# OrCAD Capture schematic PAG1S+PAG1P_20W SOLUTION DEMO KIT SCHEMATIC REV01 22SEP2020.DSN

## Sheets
1 PAGE2_REVISION HISTORY: title: CY-SD1125 CYPRESS 20W MOBILE CHARGER DEMO KIT; rev: 01; note: 630-XXXXX-XX
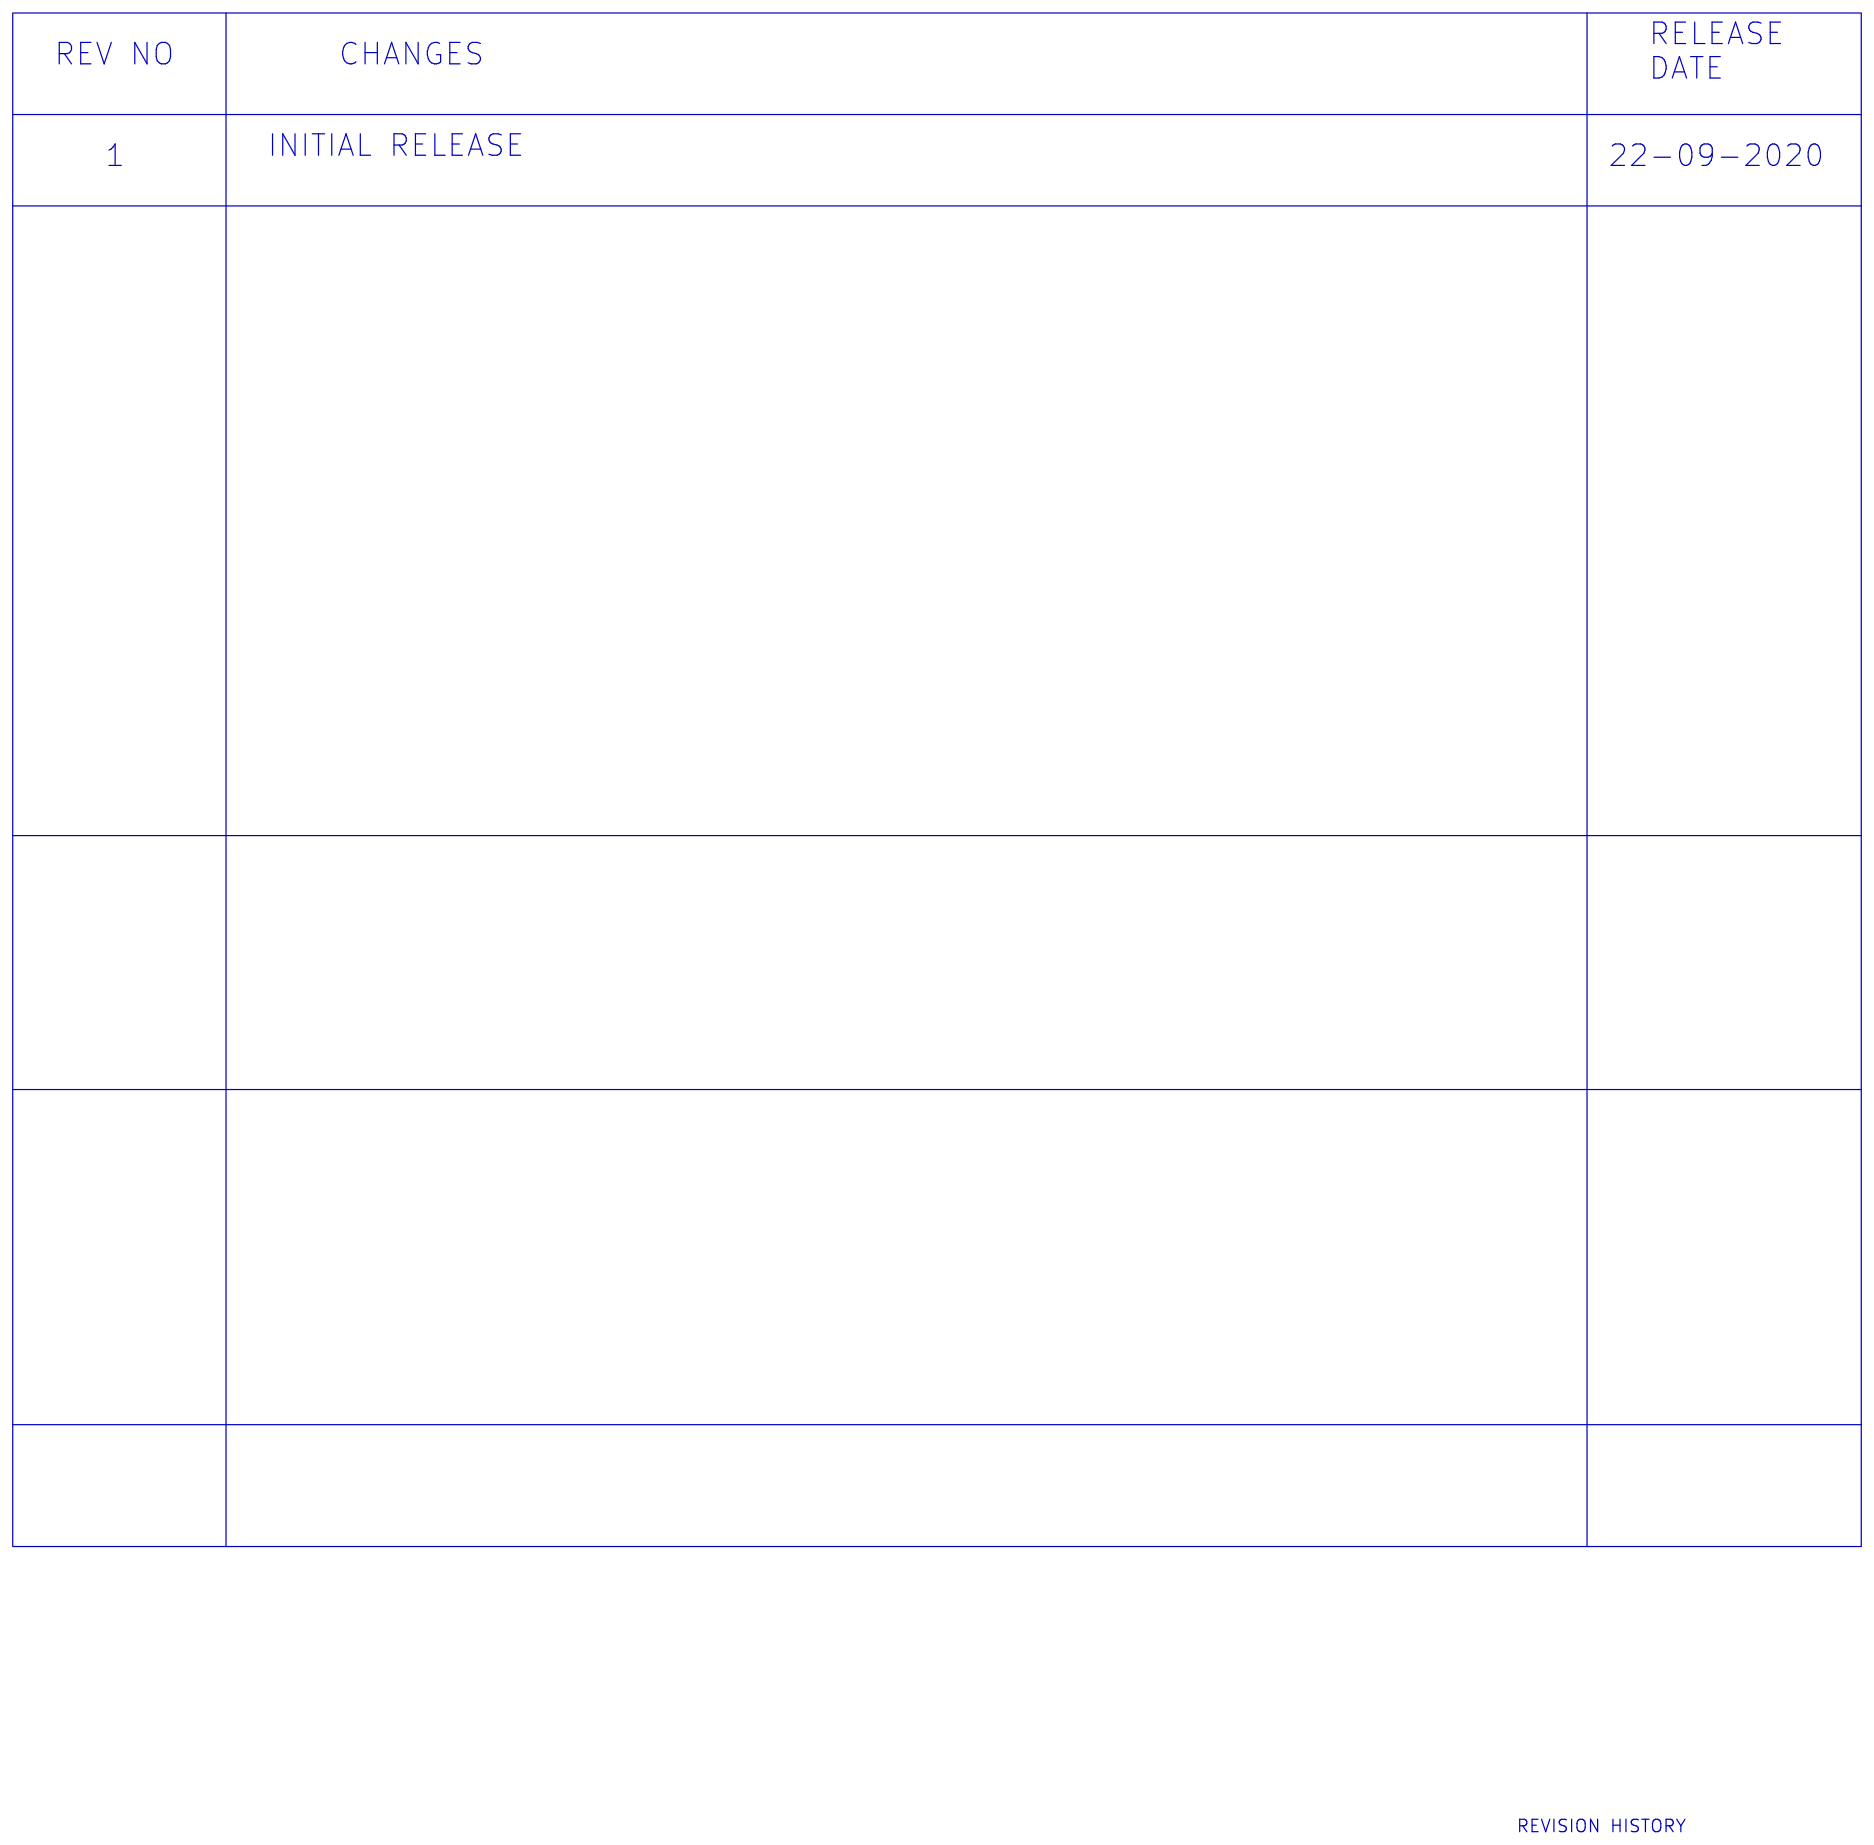
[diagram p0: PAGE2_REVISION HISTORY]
2 PAGE1_PAG1P_PAG1S: size A3
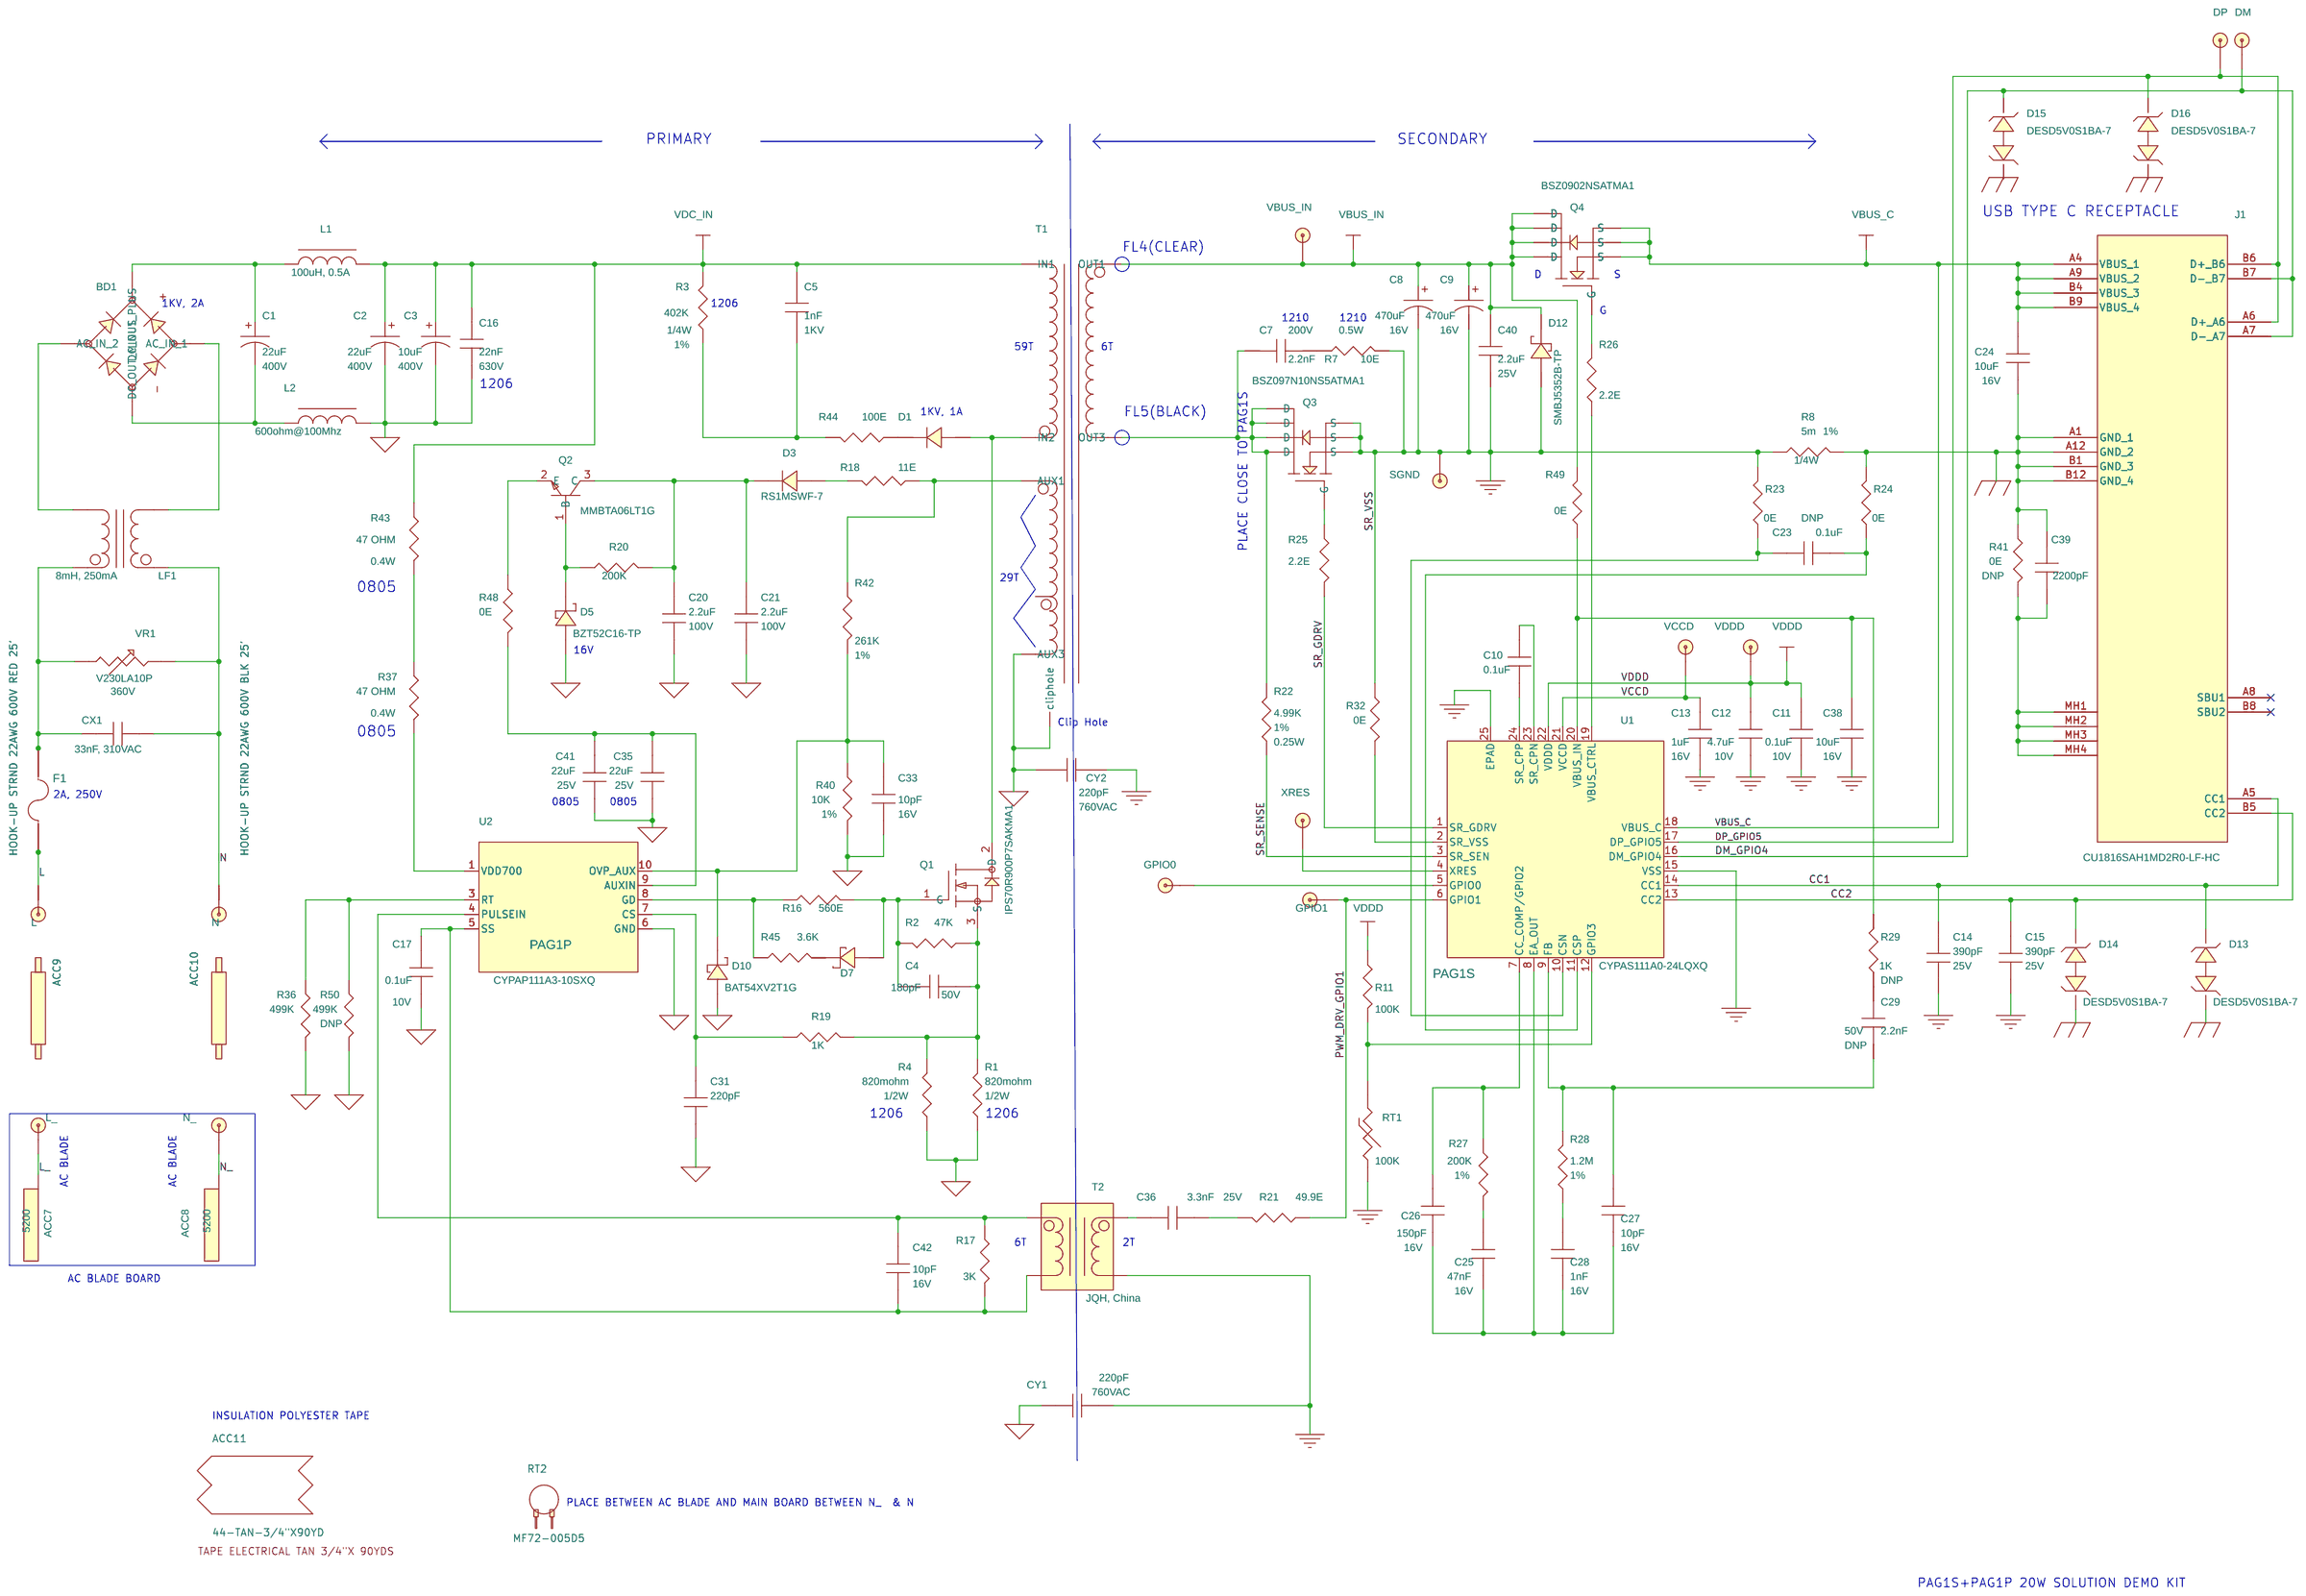
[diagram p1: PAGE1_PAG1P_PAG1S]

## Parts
ACC7  5200  [PCBBLADE]
ACC8  5200  [PCBBLADE]
ACC9  HOOK-UP STRND 22AWG 600V RED 25'
ACC10  HOOK-UP STRND 22AWG 600V BLK 25'
ACC11  44-TAN-3/4"X90YD
BD1  ABS210-13  [SOPA4P400_505X640X170L100X60]
C1  22uF  [CAPPRD600W60D1000H2150]
C2  22uF  [CAPPRD600W60D1000H2150]
C3  10uF  [CAPPRD600W60D1000H2150]
C4  180pF  [capc1608x90n_ty]
C5  1nF  [capc2012x70n_murata]
C7  2.2nF  [1210]
C8  470uF  [CAPPRD250W50D630H1400]
C9  470uF  [CAPPRD250W50D630H1400]
C10  0.1uF  [CAPC1005X56N_CYPS]
C11  0.1uF  [CAPC1005X56N_CYPS]
C12  4.7uF  [CAPC1005X56N_CYPS]
C13  1uF  [CAPC1005X56N_CYPS]
C14  390pF  [CAPC1005X56N_CYPS]
C15  390pF  [CAPC1005X56N_CYPS]
C16  22nF  [SMD_1206]
C17  0.1uF  [capc1608x90n_ty]
C20  2.2uF  [SMD_1206]
C21  2.2uF  [SMD_1206]
C23  0.1uF  [capc1608x90n_ty]
C24  10uF  [capc1608x90n_ty]
C25  47nF  [CAPC1005X56N_CYPS]
C26  150pF  [CAPC1005X56N_CYPS]
C27  10pF  [CAPC1005X56N_CYPS]
C28  1nF  [CAPC1005X56N_CYPS]
C29  2.2nF  [CAPC1005X56N_CYPS]
C31  220pF  [capc1608x90n_ty]
C33  10pF  [capc1608x90n_ty]
C35  22uF  [capc2012x70n_murata]
C36  3.3nF  [CAPC1608X90N_TY]
C38  10uF  [SMD_1206]
C39  2200pF  [capc1608x90n_ty]
C40  2.2uF  [capc2012x70n_murata]
C41  22uF  [capc2012x70n_murata]
C42  10pF  [capc1608x90n_ty]
CX1  33nF, 310VAC  [BFC233820333]
CY1  220pF  [CAPRB750W60L1400T500H1600]
CY2  220pF  [CAPRB750W60L1400T500H1600]
D1  CGRKM4007-HF  [SODFL350X180X115L60X107N]
D3  RS1MSWF-7  [SODFL350X180X115L60X107N]
D5  BZT52C16-TP  [BZT52C12-TP_SOD123]
D7  BAT54J,115  [SODFL250X125X90L60X30N]
D10  BAT54XV2T1G  [BAT54XV2T1G_SOD523]
D12  SMBJ5352B-TP  [DO214AA_MICRO]
D13  DESD5V0S1BA-7  [SOD250X130X110L30X30N]
D14  DESD5V0S1BA-7  [SOD250X130X110L30X30N]
D15  DESD5V0S1BA-7  [SOD250X130X110L30X30N]
D16  DESD5V0S1BA-7  [SOD250X130X110L30X30N]
DM  TEST_POINT  [TP-43R_S]
DP  TEST_POINT  [TP-43R_S]
F1  RSTA 2 AMMO  [FUSRR508W62L885T450H790]
GPIO0  TEST_POINT  [TP-43R_S]
GPIO1  TEST_POINT  [TP-43R_S]
J1  CU1816SAH1MD2R0-LF-HC  [USB-PD_TYPE-C]
L  TEST_POINT  [TP-43R_S]
L1  100uH, 0.5A  [INDRD300W60D800H10001]
L2  600ohm@100Mhz  [resc2012x70n_pec]
L_  TEST_POINT  [TP-43R_S]
LF1  8mH, 250mA  [L3]
N  TEST_POINT  [TP-43R_S]
N_  TEST_POINT  [TP-43R_S]
Q1  IPS70R900P7SAKMA1  [to229p230x654x875-3b]
Q2  MMBTA06LT1G  [SOT23-3P95_240X100L40X44N]
Q3  BSZ097N10NS5ATMA1  [TSDSON65P330X330X110-8N_A]
Q4  BSZ0902NSATMA1  [TSDSON65P330X330X110-8N_A]
R1  820mohm  [resc3216x65n_rohm]
R2  47K  [resc1608x55n_pec]
R3  402K  [RESC3216X65N_ROHM]
R4  820mohm  [resc3216x65n_rohm]
R7  10E  [1210]
R8  5m  [resc3216x65n_rohm]
R11  100K  [resc1608x55n_pec]
R16  560E  [resc1608x55n_pec]
R17  3K  [resc1608x55n_pec]
R18  11E  [RESC1608X55N_PEC]
R19  1K  [resc1608x55n_pec]
R20  200K  [resc1608x55n_pec]
R21  49.9E  [resc1608x55n_pec]
R22  4.99K  [resc1608x55n_pec]
R23  0E  [resc1005x40n_pec]
R24  0E  [resc1005x40n_pec]
R25  2.2E  [resc1608x55n_pec]
R26  2.2E  [resc1608x55n_pec]
R27  200K  [resc1005x40n_pec]
R28  1.2M  [resc1005x40n_pec]
R29  1K  [RESC1005X40N_PEC]
R32  0E  [resc1608x55n_pec]
R36  499K  [resc1608x55n_pec]
R37  47 OHM  [resc2012x70n_pec]
R40  10K  [resc1608x55n_pec]
R41  0E  [RESC1608X55N_PEC]
R42  261K  [RESC1608X55N_PEC]
R43  47 OHM  [resc2012x70n_pec]
R44  100E  [RESC2012X70N_PEC]
R45  3.6K  [resc1608x55n_pec]
R48  0E  [RESC1608X55N_PEC]
R49  0E  [RESC1005X40N_PEC]
R50  499K  [RESC1005X40N_PEC]
RT1  100K  [resc2012x70n_pec]
RT2  MF72-005D5
SGND  TEST_POINT  [TP-43R_S]
T1  RM7  [RM7]
T2  1:3  [RADIAL_R113426000]
U1  PAG1S  [QFN50P400X400X60-25T275X275N]
U2  PAG1P  [SOIC100P600X175-10N_CYPS]
VBUS_IN  TEST_POINT  [TP-43R_S]
VCCD  TEST_POINT  [TP-43R_S]
VDDD  TEST_POINT  [TP-43R_S]
VR1  V230LA10P
XRES  TEST_POINT  [TP-43R_S]

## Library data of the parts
ACC7 ACC8 = HEYCO_PCB_BLADE_5201_0: PCB BLADE SNAP THRU POLARIZED; Manufacturer: Heyco
ACC9 = HOOK-UP_STRND_26AWG_600V_RED: DIGIKEY-PART NUMBER: CN150R-25-ND; MFG Part number: 11047-22-1-0500-004-1-TS; Manufacturer: CNC Tech; Price: 9.15
ACC10 = HOOK-UP_STRND_26AWG_600V_RED: DIGIKEY-PART NUMBER: CN150B-25-ND; MFG Part number: 11047-22-1-0500-001-1-TS; Manufacturer: CNC Tech; Price: 9.15
ACC11 = INSULATION_POLYESTER_TAPE: TAPE ELECTRICAL TAN 3/4"X 90YDS; DIGIKEY-PART NUMBER: 3M157336-ND; Manufacturer: 3M; Price: 19.69
BD1 = BR805D_1: BRIDGE RECT 1PHASE 1KV 2A 4SOPA; DIGIKEY-PART NUMBER: ABS210-13DICT-ND; Manufacturer: Diodes Incorporated; PRICE: 0.5
C1 = CAP_2: CAP ALUM 22uF 400V RADIAL DIA 10X16; MFG Part number: EHS2GM220G16OT; Manufacturer: AISHI; Manufaturer: AISHI; Package: RAD; Voltage: 400V
C2 = CAP_2: CAP ALUM 22uF 400V RADIAL DIA 10X16; MFG Part number: EHS2GM220G16OT; Manufacturer: AISHI; Manufaturer: Rubycon; Package: RAD; Voltage: 400V
C3 = CAP_2: CAP ALUM 10uF 400V RADIAL DIA 10X12.5; Manufaturer: Rubycon; Package: RAD; Voltage: 400V
C4 = 0_0.01uF-50V-10%-X7R-0603: CAP CER 180PF 50V C0G/NPO 0603; DIGIKEY-PART NUMBER: 311-1072-1-ND; MFG Part number: CC0603JRNPO9BN181; Manufacturer: Yageo; Price: 0.1; Voltage: 50V
C5 = 0_0.01uF-50V-10%-X7R-0603: CAP CER 1000PF 1KV X7R 0805; DIGIKEY-PART NUMBER: 399-7137-1-ND; MFG Part number: C0805C102MDRACTU; Manufacturer: KEMET; Price: 0.41; TOLERANCE: <Tolerance>; Voltage: 1KV
C7 = 0_0.01uF-50V-10%-X7R-0603: CAP CER 2200PF 200V NP0 1210; Assy: DNP; DIGIKEY-PART NUMBER: 399-15600-1-ND; MFG Part number: C1210C222J2GAC7800; Manufacturer: KEMET; Price: 0.94; TOLERANCE: <Tolerance>; Voltage: 200V
C8 C9 = CAP_2: CAP POLYMER 470uF 16V 6.3x11; MFG Part number: SPF1CM471E11O00RAXXX; Manufacturer: AISHI; Package: RAD; RATED_VOLTAGE: 16V
C10 C11 = 0_0.01uF-50V-10%-X7R-0603: CAP CER 0.1UF 10V X5R 0402; DIGIKEY-PART NUMBER: 1276-1443-1-ND; MFG Part number: CL05A104MP5NNNC; Manufacturer: Samsung Electro-Mechanics; Price: 0.1; Voltage: 10V
C12 = 0_0.01uF-50V-10%-X7R-0603: CAP CER 4.7UF 10V X5R 0402; DIGIKEY-PART NUMBER: 490-14306-1-ND; MFG Part number: GRM155R61A475MEAAD; Manufacturer: Murata Electronics North America; Price: 0.23; Voltage: 10V
C13 = 0_0.01uF-50V-10%-X7R-0603: CAP CER 1UF 16V X5R 0402; DIGIKEY-PART NUMBER: 1276-1447-1-ND; MFG Part number: CL05A105MO5NNNC; Manufacturer: Samsung Electro-Mechanics; Price: 0.1; Voltage: 16V
C14 C15 = 0_0.01uF-50V-10%-X7R-0603: CAP CER 390PF 25V C0G/NP0 0402; DIGIKEY-PART NUMBER: 490-14801-1-ND; MFG Part number: GRM1555C1E391JA01D; Manufacturer: Murata Electronics North America; Price: 0.13; Voltage: 25V
C16 = 0_0.01uF-50V-10%-X7R-0603: CAP CER 0.022UF 630V X7R 1206; DIGIKEY-PART NUMBER: 1276-3126-1-ND; MFG Part number: CL31B223KHHNNNE; Manufacturer: Samsung Electro-Mechanics; Price: 0.26; TOLERANCE: <Tolerance>; Voltage: 630V
C17 = 0_0.01uF-50V-10%-X7R-0603: CAP CER 0.1UF 10V X7R 0603; DIGIKEY-PART NUMBER: 311-4055-1-ND; MFG Part number: CC0603KRX7R6BB104; Manufacturer: Yageo; Price: 0.12; Voltage: 10V
C20 C21 = 0_0.01uF-50V-10%-X7R-0603: CAP CER 2.2UF 100V X5R 1206; DIGIKEY-PART NUMBER: 1276-2724-1-ND; MFG Part number: CL31A225KC9LNNC; Manufacturer: Samsung Electro-Mechanics; Price: 1.33; Voltage: 100V
C23 = 0_0.01uF-50V-10%-X7R-0603: CAP CER 0.1UF 35V X7R 0603; DIGIKEY-PART NUMBER: 587-3354-1-ND; DNP: DNP; MFG Part number: GMK107B7104KAHT; Manufacturer: Taiyo Yuden; Price: 0.16
C24 = 0_0.01uF-50V-10%-X7R-0603: CAP CER 10UF 16V X5R 0603; DIGIKEY-PART NUMBER: 490-10728-1-ND; MFG Part number: GRM188R61C106KAALD; Manufacturer: Murata Electronics; Price: 0.39; TOLERANCE: <Tolerance>; Voltage: 16V
C25 = 0_0.01uF-50V-10%-X7R-0603: CAP CER 0.047UF 16V X7R 0402; DIGIKEY-PART NUMBER: 1276-1077-1-ND; MFG Part number: CL05B473KO5NNNC; Manufacturer: Samsung Electro-Mechanics; Price: 0.1; Voltage: 16V
C26 = 0_0.01uF-50V-10%-X7R-0603: CAP CER 150PF 16V X7R 0402; DIGIKEY-PART NUMBER: 732-7515-1-ND; MFG Part number: 885012205020; Manufacturer: Wurth Electronics Inc.; PART_NUMBER: 885012205020; Price: 0.1; Voltage: 16V
C27 = 0_0.01uF-50V-10%-X7R-0603: CAP CER 10PF 16V C0G/NP0 0402; DIGIKEY-PART NUMBER: 732-7441-1-ND; MFG Part number: 885012005025; Manufacturer: Wurth Electronics Inc.; Price: 0.1; Voltage: 16V
C28 = 0_0.01uF-50V-10%-X7R-0603: CAP CER 1000PF 16V X7R 0402; DIGIKEY-PART NUMBER: 399-7755-1-ND; MFG Part number: C0402C102K4RACTU; Manufacturer: KEMET; Price: 0.1; Voltage: 16V
C29 = 0_0.01uF-50V-10%-X7R-0603: CAP CER 2200PF 50V X7R 0402; DIGIKEY-PART NUMBER: 490-4914-1-ND; DNP: DNP; MFG Part number: GCM155R71H222KA37D; Manufacturer: Murata Electronics North America; Price: 0.10; TOLERANCE: <Tolerance>; Voltage: 50V
C31 = 0_0.01uF-50V-10%-X7R-0603: CAP CER 220PF 10V C0G/NP0 0603; DIGIKEY-PART NUMBER: 399-14963-1-ND; MFG Part number: C0603C221J8GAC7867; Manufacturer: KEMET; Price: 0.39; Voltage: 10V
C33 C42 = 0_0.01uF-50V-10%-X7R-0603: CAP CER 10PF 16V C0G/NP0 0603; DIGIKEY-PART NUMBER: 732-7760-1-ND; MFG Part number: 885012006017; Manufacturer: Wurth Electronics Inc.; Price: 0.1; Voltage: 16V
C35 C41 = 0_0.01uF-50V-10%-X7R-0603: CAP CER 22UF 25V X5R 0805; DIGIKEY-PART NUMBER: 490-14661-1-ND; MFG Part number: GRM21BR61E226ME44K; Manufacturer: Murata Electronics North America; Price: 0.49; Voltage: 25V
C36 = 0_0.01uF-50V-10%-X7R-0603: CAP CER 3300PF 25V NP0 0603; DIGIKEY-PART NUMBER: 399-15394-1-ND; MFG Part number: C0603C332J3GAC7867; Manufacturer: KEMET; Price: 0.4; TOLERANCE: C0G/NPO; Voltage: 25V
C38 = 0_0.01uF-50V-10%-X7R-0603: CAP CER 10UF 16V X7R 1206; DIGIKEY-PART NUMBER: 1276-6641-1-ND; MFG Part number: CL31B106MOHNNNE; Manufacturer: Samsung Electro-Mechanics; Price: 0.26; TOLERANCE: <Tolerance>; Voltage: 16V
C39 = 0_0.01uF-50V-10%-X7R-0603: CAP CER 2200PF 500V X7R 0603; DIGIKEY-PART NUMBER: 399-14966-1-ND; MFG Part number: C0603C222KCRAC7867; Manufacturer: KEMET; Price: 0.3; TOLERANCE: <Tolerance>; Voltage: 500V
C40 = 0_0.01uF-50V-10%-X7R-0603: CAP CER 2.2UF 25V X5R 0805; DIGIKEY-PART NUMBER: 1276-6458-1-ND; MFG Part number: CL21A225KAFNNNG; Manufacturer: Samsung Electro-Mechanics; Price: 0.17; TOLERANCE: <Tolerance>; Voltage: 25V
CX1 = 0_0.01uF-50V-10%-X7R-0603: CAP FILM 0.033UF 20% 630VDC RAD; DIGIKEY-PART NUMBER: BC1612-ND; Manufacturer: Vishay BC Components; Package: RAD; Price: 1.27; TOLERANCE: <Tolerance>; Voltage: 310VAC
CY1 CY2 = 0_0.01uF-50V-10%-X7R-0603: CAP CER 220PF 760VAC Y5S RADIAL; Assy: DNP; DIGIKEY-PART NUMBER: BC2370-ND; MFG Part number: VY1221K31Y5SQ63V0; Manufacturer: Vishay BC Components; Package: RAD; Price: 0.3; Voltage: 760VAC
D1 = DIODE_13: DIODE GEN PURP 1KV 1A SOD123F; DIGIKEY-PART NUMBER: 641-1514-1-ND; Manufacturer: Comchip Technology; PRICE: 0.36
D3 = DIODE_17: DIODE GEN PURP 1KV 1A SOD123F; DIGIKEY-PART NUMBER: RS1MSWF-7DICT-ND; Manufacturer: Diodes Incorporated; Price: 0.52
D5 = DIODE_SCHOTTKY_19: DIODE ZENER 16V 200MW SOD123; DIGIKEY-PART NUMBER: BZT52C16-TPMSCT-ND; Manufacturer: Micro Commercial Co; Price: 0.21
D7 = DIODE_18: DIODE SCHOTTKY 30V 200MA SOD323F; DIGIKEY-PART NUMBER: 1727-4818-1-ND; Manufacturer: Nexperia USA Inc.; PRICE: 0.33
D10 = DIODE_SCHOTTKY_21: DIODE SCHOTTKY 30V 200MA SOD523; DIGIKEY-PART NUMBER: BAT54XV2T1GOSCT-ND; Manufacturer: ON Semiconductor; Price: 0.23
D12 = DIODE_SCHOTTKY_19: DIODE ZENER 15V 5W DO214AA; DIGIKEY-PART NUMBER: SMBJ5352B-TPMSCT-ND; Manufacturer: Micro Commercial Co; Price: 0.65
D13-D16 = TVS_DIODE_1: TVS DIODE 5V 14V SOD323; DIGIKEY-PART NUMBER: DESD5V0S1BA-7DICT-ND; Manufacturer: Diodes Incorporated; Price: 0.36
DM DP GPIO0 GPIO1 L L_ N N_ SGND VBUS_IN VCCD VDDD XRES = TEST_POINT
F1 = Fuse_2: FUSE BRD MNT 2A 250VAC/63VDC RAD; DIGIKEY-PART NUMBER: 507-1868-1-ND; LatestRevisionDate: 17-Jul-2002; LatestRevisionNote: Re-released for DXP Platform.; Manufacturer: Bel Fuse Inc.; PRICE: 0.32; PackageReference: PIN-W2/E2.8; Published: 8-Jun-2000; Publisher: Altium Limited
J1 = USB-PD_TYPE-C_7: CU18 USB Type-C Receptacle Connector; Manufacturer: CviLux Corporation
L1 = INDUCTOR_PAG1S_1: 100uH D8x10mm 0.5A; Current: 300mA; Manufacturer: Prismatic
L2 = INDUCTOR_PAG1S_1: FERRITE BEAD 600 OHM 0805 1LN; Current: 300mA; DIGIKEY-PART NUMBER: 732-1620-1-ND; MFG Part number: 742792040; Manufacturer: Wurth Electronics Inc.; Manufaturer: Bourns Inc.; PRICE: 0.22
LF1 = INDUCTOR_IRON_8: 8mH / D18.5 * T7.5mm*H18.5 / 250mA; MFG Part number: 9404320301; Manufacturer: Prismatic
Q1 = IPP65R380E6XKSA1_1: MOSFET N-CHANNEL 700V 6A TO251; DIGIKEY-PART NUMBER: IPS70R900P7SAKMA1-ND; Manufacturer: Infineon Technologies
Q2 = 2N1070_1: TRANS NPN 80V 0.5A SOT23; DIGIKEY-PART NUMBER: MMBTA06LT1GOSCT-ND; Manufacturer: ON Semiconductor; Price: 0.23
Q3 = DMTH10H010LCT_5: MOSFET N-CH 100V 40A TSDSON-8; DIGIKEY-PART NUMBER: BSZ097N10NS5ATMA1CT-ND; Manufacturer: Infineon Technologies; PRICE: 1.75
Q4 = DMTH10H010LCT_5: MOSFET N-CH 30V 40A TSDSON-8; DIGIKEY-PART NUMBER: BSZ0902NSATMA1CT-ND; Manufacturer: Infineon Technologies; PRICE: 1.04
R1 = RESISTOR: RES 0.82 OHM 1% 1/2W 1206; DIGIKEY-PART NUMBER: RCWE.82ECT-ND; MFG Part number: RCWE1206R820FKEA; Manufacturer: Vishay Dale; Package: 2010; Price: 0.61; Wattage: 1/2W
R2 = RESISTOR: RES SMD 47K OHM 1% 1/10W 0603; DIGIKEY-PART NUMBER: 311-47.0KHRCT-ND; MFG Part number: RC0603FR-0747KL; Manufacturer: Yageo; Price: 0.1
R3 = RESISTOR: RES SMD 402K OHM 1% 1/4W 1206; DIGIKEY-PART NUMBER: 311-402KFRCT-ND; MFG Part number: RC1206FR-07402KL; Manufacturer: Yageo; Package: 1206; Price: 0.1; Tolerance: 1%; Wattage: 1/4W
R4 = RESISTOR: RES 0.82 OHM 1% 1/2W 1206; Assy: DNP; DIGIKEY-PART NUMBER: RCWE.82ECT-ND; MFG Part number: RCWE1206R820FKEA; Manufacturer: Vishay Dale; Package: 2010; Price: 0.61; Wattage: 1/2W
R7 = RESISTOR: RES 10 OHM 1% 1/2W 1210; Assy: DNP; DIGIKEY-PART NUMBER: RMCF1210FT10R0CT-ND; MFG Part number: RMCF1210FT10R0; Manufacturer: Stackpole Electronics Inc; Price: 0.15; VOLTAGE: 0.5W
R8 = RESISTOR: RES 0.005 OHM 1% 1W 1206; DIGI-KEY PART NO: CSRF1206FT5L00CT-ND; DIGIKEY-PART NUMBER: CSRF1206FT5L00CT-ND; MFG Part number: CSRF1206FT5L00; Manufacturer: Stackpole Electronics Inc.; PART_NUMBER: PRL1632-R005-F-T1; Package: 1206; Price: 0.66; Tolerance: 1%; Wattage: 1/4W
R11 = 330_ohm_5%_0805_0: RES SMD 100K OHM 1% 1/10W 0603; DIGIKEY-PART NUMBER: P100KHCT-ND; MFG Part number: ERJ-3EKF1003V; Manufacturer: Panasonic Electronic Components; PRICE: 0.1
R16 = 330_ohm_5%_0805_0: RES SMD 560 OHM 1% 1/10W 0603; DIGIKEY-PART NUMBER: P560HCT-ND; MFG Part number: ERJ-3EKF5600V; Manufacturer: Panasonic Electronic Components; PRICE: 0.1
R17 = 330_ohm_5%_0805_0: RES SMD 3K OHM 1% 1/10W 0603; DIGIKEY-PART NUMBER: 311-3.00KHRCT-ND; MFG Part number: RC0603FR-073KL; Manufacturer: Yageo; PRICE: 0.1
R18 = RESISTOR: RES SMD 11 OHM 1% 1/4W 0603; Assy: DNP; DIGIKEY-PART NUMBER: P11.00BYCT-ND; MFG Part number: ERJ-PA3F11R0V; Manufacturer: Panasonic Electronic Components; Package: 0603; Price: 0.16
R19 = 330_ohm_5%_0805_0: RES SMD 1K OHM 1% 1/10W 0603; DIGIKEY-PART NUMBER: P1.00KHCT-ND; MFG Part number: ERJ-3EKF1001V; Manufacturer: Panasonic Electronic Components; PRICE: 0.1
R20 = RESISTOR: RES SMD 200K OHM 1% 1/10W 0603; DIGIKEY-PART NUMBER: P200KHCT-ND; MFG Part number: ERJ-3EKF2003V; Manufacturer: Panasonic Electronic Components; Price: 0.1
R21 = 330_ohm_5%_0805_0: RES SMD 49.9 OHM 1% 1/10W 0603; DIGIKEY-PART NUMBER: 311-49.9HRCT-ND; MFG Part number: RC0603FR-0749R9L; Manufacturer: Yageo; PRICE: 0.1
R22 = 330_ohm_5%_0805_0: RES SMD 4.99K OHM 1% 1/4W 0603; DIGIKEY-PART NUMBER: 541-4.99KSCT-ND; MFG Part number: CRCW06034K99FKEAHP; Manufacturer: Vishay Dale; PRICE: 0.18; VOLTAGE: 1%; WATT: 0.25W; Wattage: 0.25W
R23 R24 R49 = 330_ohm_5%_0805_0: RES SMD 0 OHM JUMPER 1/10W 0402; DIGIKEY-PART NUMBER: P0.0JCT-ND; MFG Part number: ERJ-2GE0R00X; Manufacturer: Panasonic Electronic Components; Mfr_Name: Yageo; Mfr_Part#: RC0402FR-07100KL; PRICE: 0.1
R25 R26 = 330_ohm_5%_0805_0: RES SMD 2.2 OHM 1% 1/10W 0603; DIGIKEY-PART NUMBER: 311-2.2HRCT-ND; MFG Part number: RC0603FR-072R2L; Manufacturer: Yageo; Mfr_Name: Yageo; Mfr_Part#: RC0402FR-07100KL; PRICE: 0.1
R27 = 330_ohm_5%_0805_0: RES SMD 200K OHM 1% 1/16W 0402; DIGIKEY-PART NUMBER: 311-200KLRCT-ND; MFG Part number: RC0402FR-07200KL; Manufacturer: Yageo; Mfr_Name: Yageo; Mfr_Part#: RC0402FR-07200KL; PRICE: 0.1; Tolerance: 1%
R28 = 330_ohm_5%_0805_0: RES SMD 1.2M OHM 1% 1/16W 0402; DIGIKEY-PART NUMBER: YAG5649CT-ND; MFG Part number: AC0402FR-071M2L; Manufacturer: Yageo; Mfr_Name: Panasonic Electronic Components; Mfr_Part#: ERJ-2RKF4993X; PRICE: 0.1; Tolerance: 1%
R29 = 330_ohm_5%_0805_0: RES 1K OHM 1% 1/16W 0402; DIGIKEY-PART NUMBER: RMCF0402FT1K00CT-ND; DNP: DNP; MFG Part number: RMCF0402FT1K00; Manufacturer: Stackpole Electronics Inc.; Mfr_Name: Yageo; Mfr_Part#: RC0402FR-07100KL; PRICE: 0.1
R32 = 330_ohm_5%_0805_0: RES SMD 0 OHM JUMPER 1/4W 0603; DIGIKEY-PART NUMBER: 541-0.0SBCT-ND; MFG Part number: CRCW06030000Z0EAHP; Manufacturer: Vishay Dale; Mfr_Name: Yageo; Mfr_Part#: ERJ-3GEY0R00V; PRICE: 0.17
R36 = 330_ohm_5%_0805_0: RES SMD 499K OHM 1% 1/8W 0603; DIGIKEY-PART NUMBER: 749-1661-6-ND; MFG Part number: MCT06030C4993FP500; Manufacturer: Vishay Beyschlag; Mfr_Name: Vishay Beyschlag; Mfr_Part#: RC0402FR-07100KL; Mfr_Part_Number: MCT06030C4993FP500; PRICE: 0.1
R37 R43 = 330_ohm_5%_0805_0: RES SMD 47 OHM 5% 0.4W 0805; ALTERNATE PARTNUMBER 1: RHM47KCT-ND; DIGIKEY-PART NUMBER: RHM47KCT-ND; MFG Part number: ESR10EZPJ470; Manufacturer: Rohm Semiconductor; PRICE: 0.1; Wattage: 0.4W
R40 = 330_ohm_5%_0805_0: RES SMD 10K OHM 1% 1/10W 0603; DIGIKEY-PART NUMBER: 311-10.0KHRCT-ND; MFG Part number: RC0603FR-0710KL; Manufacturer: Yageo; PRICE: 0.10; VOLTAGE: 1%; Wattage: 0.1W
R41 = 330_ohm_5%_0805_0: RES SMD 0 OHM JUMPER 1/4W 0603; DIGIKEY-PART NUMBER: 541-0.0SBCT-ND; DNP: DNP; MFG Part number: CRCW06030000Z0EAHP; Manufacturer: Vishay Dale; Mfr_Name: Yageo; Mfr_Part#: RC0402FR-07100KL; PRICE: 0.17
R42 = 330_ohm_5%_0805_0: RES SMD 261K OHM 1% 1/10W 0603; DIGIKEY-PART NUMBER: 311-261KHRCT-ND; MFG Part number: RC0603FR-07261KL; Manufacturer: Yageo; PRICE: 0.1; Tolerance: 1%
R44 = 330_ohm_5%_0805_0: RES 100 OHM 1% 1/4W 0805; DIGIKEY-PART NUMBER: RNCP0805FTD100RCT-ND; MFG Part number: RNCP0805FTD100R; Manufacturer: Stackpole Electronics Inc; PRICE: 0.1
R45 = 330_ohm_5%_0805_0: RES SMD 3.6K OHM 1% 1/10W 0603; DIGIKEY-PART NUMBER: P3.60KHCT-ND; MFG Part number: ERJ-3EKF3601V; Manufacturer: Panasonic Electronic Components; Mfr_Name: Yageo; Mfr_Part#: RC0402FR-07100KL; PRICE: 0.1
R48 = 330_ohm_5%_0805_0: RES SMD 0 OHM JUMPER 1/4W 0603; DIGIKEY-PART NUMBER: 541-0.0SBCT-ND; MFG Part number: CRCW06030000Z0EAHP; Manufacturer: Vishay Dale; Mfr_Name: Yageo; Mfr_Part#: RC0402FR-07100KL; PRICE: 0.17
R50 = 330_ohm_5%_0805_0: RES SMD 499K OHM 1% 1/10W 0402; DIGIKEY-PART NUMBER: P499KLCT-ND; DNP: DNP; MFG Part number: ERJ-2RKF4993X; Manufacturer: Panasonic Electronic Components; Mfr_Name: Vishay Beyschlag; Mfr_Part#: RC0402FR-07100KL; Mfr_Part_Number: MCT06030C4993FP500; PRICE: 0.1
RT1 = RESISTOR_VAR_2_4: THERM NTC 100KOHM 4250K 0805; DIGIKEY-PART NUMBER: 490-2451-1-ND; MFG Part number: NCP21WF104J03RA; Manufacturer: Murata Electronics North America; Manufaturer: Cantherm; PRICE: 0.21
RT2 = MF72-005D5: ICL 5 OHM 20% 1A 7MM; DIGIKEY-PART NUMBER: 317-1144-ND; Manufacturer: Cantherm
T1 = PA5222NL_35: RM7 Transformer; MFG Part number: BCK0RM3752B1; Manufacturer: Shenzhen Jingquanhua (JQH) Electronics Co. Ltd
T2 = TRANSFORMER_11: Pulse transformer, 1:3, 4.8uH, 3KV isolation voltage; MFG Part number: LCL-T6-4961A; Manufacturer: JQH, China
U1 = PAG1S_11: USB-PD Power Adapter Secondary Side Controller; MFG Part number: CYPAS111A0-24LQXQ; Manufacturer: CYPRESS SEMICONDUCTOR
U2 = PAG1P_3: PRIMARY SIDE STARTUP CONTROLLER; MFG Part number: CYPAP111A3-10SXQ; Manufacturer: CYPRESS SEMICONDUCTOR
VR1 = RESISTOR_VAR_2_0: VARISTOR 360V 2.5KA DISC 10MM; DIGIKEY-PART NUMBER: V230LA10P-ND; Manufacturer: Littelfuse Inc.; Manufaturer: Littelfuse Inc.; Price: 0.57; Voltage: 360V

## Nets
VBUS_C: C24.1 J1.A4(VBUS_1) J1.A9(VBUS_2) J1.B4(VBUS_3) J1.B9(VBUS_4) Q4.1(S) Q4.2(S) Q4.3(S) U1.18(VBUS_C)
VBUS_IN: C8.1 C9.1 C40.1 D12.K Q4.5(D) Q4.6(D) Q4.7(D) Q4.8(D) R49.2 T1.10(OUT1) VBUS_IN.1
VCCD: C13.1 U1.21(VCCD) VCCD.1
VDDD: C11.1 C12.1 R11.2 U1.22(VDDD) VDDD.1
CC1: C14.1 D13.C J1.A5(CC1) U1.14(CC1)
CC2: C15.1 D14.C J1.B5(CC2) U1.13(CC2)
DM_GPIO4: D15.C DM.1 J1.A7(D-) J1.B7(D-) U1.16(DM_GPIO4)
DP_GPIO5: D16.C DP.1 J1.A6(D+) J1.B6(D+) U1.17(DP_GPIO5)
L: F1.2 L.1
L_: ACC7.1 L_.1
N: CX1.2 LF1.1 N.1 VR1.2
N_: ACC8.1 N_.1
PE_GND: C2.2 C3.2 C16.2 C17.2 C20.2 C21.2 C31.2 C33.2 C35.2 C41.2 CY1.1 CY2.1 D5.A D10.A L2.2 R1.2 R4.2 R36.1 R40.1 R50.1 T1.2(AUX3) T1.11(cliphole) U2.6(GND)
PWM_DRV_GPIO1: GPIO1.1 R21.1 U1.6(GPIO1)
SE_GND: C8.2 C9.2 C11.2 C12.2 C13.2 C14.2 C15.2 C38.2 C40.2 CY1.2 CY2.2 D12.A Q3.1(S) Q3.2(S) Q3.3(S) R7.1 R8.2 R23.2 R32.2 RT1.1 SGND.1 T2.2 U1.15(VSS) U1.25(EPAD)
SR_GDRV: R25.1 U1.1(SR_GDRV)
SR_SENSE: R22.1 U1.3(SR_SEN)
TYPE-C_GND: C24.2 C39.1 D13.A D14.A D15.A D16.A J1.A1(GND_1) J1.A12(GND_2) J1.B1(GND_3) J1.B12(GND_4) R8.1 R24.2 R41.2
VDC_IN: C2.1 C3.1 C5.1 C16.1 L1.2 R3.1 R43.2 T1.1(IN1)
N14611440: CX1.1 F1.1 LF1.2 VR1.1
N14642330: BD1.4(AC_IN_2) LF1.3
N14642346: BD1.2(AC_IN_1) LF1.4
N14642513: BD1.1(DC_OUT_PLUS) C1.1 L1.1
N14642535: BD1.3(DC_OUT_MINUS) C1.2 L2.1
N14649078: C7.1 Q3.5(D) Q3.6(D) Q3.7(D) Q3.8(D) R22.2 T1.9(OUT3)
N14679612: Q4.4(G) R26.2
N14684319: R11.1 RT1.2 U1.12(GPIO3)
N14693071: C23.1 R23.1 U1.10(CSN)
N14693222: C23.2 R24.1 U1.11(CSP)
N14693774: GPIO0.1 U1.5(GPIO0)
N14694144: C25.2 C26.2 C27.2 C28.2 U1.8(EA_OUT)
N14694182: C26.1 R27.2 U1.7(CC_COMP/GPIO2)
N14694200: C27.1 C29.2 R28.2 U1.9(FB)
N14702573: C38.1 R29.2 R49.1 U1.20(VBUS_IN)
N14702669: C10.2 U1.24(SR_CPP)
N14702673: C10.1 U1.23(SR_CPN)
N14714455: U1.4(XRES) XRES.1
N14737770: R32.1 U1.2(SR_VSS)
N14785175: D5.K Q2.1(B) R20.2
N14785189: C20.1 C21.1 D3.C Q2.3(C) R20.1
N14787619: Q2.2(E) R48.2
N14787638: D1.A Q1.2(D) T1.7(IN2)
N14791099: C35.1 C41.1 R48.1 U2.9(AUXIN)
N14814894: C5.2 R3.2 R44.2
N14820915: C39.2 J1.MH1 J1.MH2 J1.MH3 J1.MH4 R41.1
N14862097: C4.1 D7.A Q1.1(G) R2.2 R16.2
N14862239: R16.1 R45.1 U2.8(GD)
N14862483: C17.1 C42.2 R17.2 T2.4 U2.5(SS)
N14862590: C42.1 R17.1 T2.3 U2.4(PULSEIN)
N14862769: C31.1 R19.1 U2.7(CS)
N14862985: R37.1 U2.1(VDD700)
N14865019: C33.1 D10.C(K) R40.2 R42.1 U2.10(OVP_AUX)
N14871077: C4.2 Q1.3(S) R1.1 R2.1 R4.1 R19.2
N14908282: R36.2 R50.2 U2.3(RT)
N14923159: R37.2 R43.1
N14933197: R26.1 U1.19(VBUS_CTRL)
N14933813: D3.A R18.1
N14956400: D7.C R45.2
N14974360: C36.2 R21.2
N14974376: C36.1 T2.1
N14975051: C28.1 R28.1
N14975285: C25.1 R27.1
N14978138: Q3.4(G) R25.2
N14987684: R18.2 R42.2 T1.3(AUX1)
N15980871: C7.2 R7.2
N15980872: C29.1 R29.1
N15980873: D1.C R44.1

Not connected (* = marked no-connect by the designer): J1 A8(SBU1)* B8(SBU2)*

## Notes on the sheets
sheet 1
- RELEASE
  DATE
- REV NO
- CHANGES
- 1
- INITIAL RELEASE
- 22-09-2020
- REVISION HISTORY
sheet 2
- PRIMARY
- SECONDARY
- USB TYPE C RECEPTACLE
- FL4(CLEAR)
- D
- S
- 1KV, 2A
- 1206
- 1210
- 1210
- G
- 59T
- 6T
- 1206
- 1KV, 1A
- FL5(BLACK)
- PLACE CLOSE TO PAG1S
- 0805
- 29T
- 16V
- 0805
- Clip Hole
- 2A, 250V
- 0805
- 0805
- 1206
- 1206
- AC BLADE
- AC BLADE
- 6T
- 2T
- AC BLADE BOARD
- INSULATION POLYESTER TAPE
- PLACE BETWEEN AC BLADE AND MAIN BOARD BETWEEN N_  & N
- PAG1S+PAG1P 20W SOLUTION DEMO KIT
